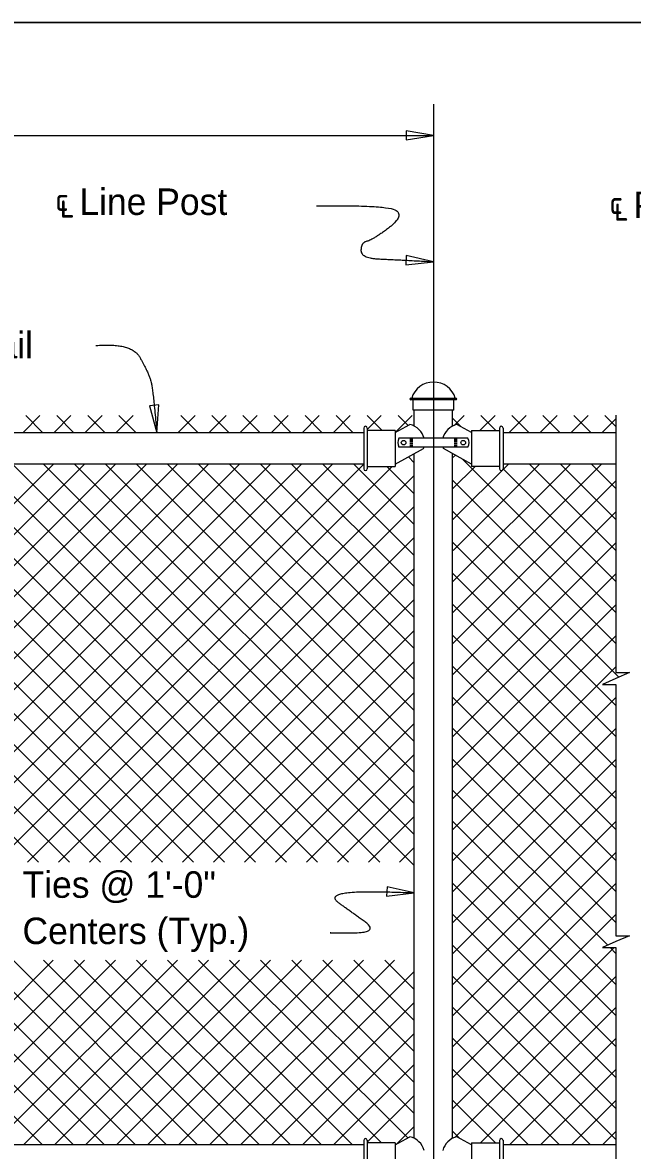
# Model space of a CAD drawing. Extents: x 0 to 41.1, y 0 to 25.9.
# Drawn here: x 18.95 to 23.59, y 17.37 to 25.95 of the extents above; entities that cross this region are included whole.
import ezdxf

# ---------------------------------------------------------------- set-up
doc = ezdxf.new("R2010")
doc.units = 0
for name, color, linetype in [('ActivePts-ConstElements', 7, 'Continuous'), ('CL_Major', 7, 'Continuous'), ('Dimension', 7, 'Continuous'), ('Miscellaneous', 7, 'Continuous'), ('Miscellaneous1', 7, 'Continuous'), ('SteelMisc', 7, 'Continuous'), ('TextStructures', 7, 'Continuous')]:
    doc.layers.add(name, color=color, linetype=linetype)

msp = doc.modelspace()

# ---------------------------------------------------------------- linework, layer by layer
at = {"layer": 'ActivePts-ConstElements'}
msp.add_lwpolyline([(0, 0), (41.0506, 0), (41.0506, 25.9461), (0, 25.9461)], close=True, dxfattribs=at)
at = {"layer": 'CL_Major'}
msp.add_line((22.075, 25.3255), (22.075, 16.5436), dxfattribs=at)
at = {"layer": 'Dimension'}
msp.add_line((2.075, 25.0883), (22.075, 25.0883), dxfattribs=at)
for points in [[(22.075, 25.0884), (21.8668, 25.1237), (21.8668, 25.0531)], [(22.075, 24.1273), (21.869, 24.1739), (21.8652, 24.1035)], [(19.9724, 22.8271), (19.9882, 23.0378), (19.9179, 23.0312)], [(21.9293, 19.3283), (21.7227, 19.3721), (21.7198, 19.3016)]]:
    msp.add_lwpolyline(points, close=True, dxfattribs=at)
for points in [[(23.462, 22.9593), (23.462, 21.0031), (23.5654, 21.0031), (23.462, 20.9581), (23.3587, 20.9131), (23.462, 20.9131), (23.462, 20.0194)], [(23.462, 20.0194), (23.462, 19.0017), (23.5654, 19.0017), (23.462, 18.9567), (23.3587, 18.9117), (23.462, 18.9117), (23.462, 16.9573)]]:
    msp.add_lwpolyline(points, dxfattribs=at)
for points in [[(21.1855, 24.5511), (21.7313, 24.5609), (21.8537, 24.472), (21.6095, 24.2907), (21.5247, 24.2723), (21.5247, 24.1544), (21.8027, 24.1422), (22.075, 24.1273)], [(19.5105, 23.4901), (19.7822, 23.5125), (19.9084, 23.2854), (19.9452, 23.1638), (19.9724, 22.827)], [(21.2967, 19.0236), (21.2533, 19.0236), (21.6734, 19.0236), (21.4231, 19.2007), (21.286, 19.3034), (21.4965, 19.3459), (21.9292, 19.3281)]]:
    msp.add_open_spline(points, degree=2, dxfattribs=at)
at = {"layer": 'Miscellaneous'}
for p, q in [((18.9555, 22.8271), (19.0857, 22.9573)), ((18.9782, 22.9573), (19.1084, 22.8271)), ((19.1912, 22.8271), (19.3214, 22.9573)), ((19.2139, 22.9573), (19.3441, 22.8271)), ((19.4269, 22.8271), (19.5571, 22.9573)), ((19.4496, 22.9573), (19.5798, 22.8271)), ((19.6626, 22.8271), (19.7928, 22.9573)), ((19.6853, 22.9573), (19.8155, 22.8271)), ((20.134, 22.8271), (20.2642, 22.9573)), ((20.1567, 22.9573), (20.2869, 22.8271)), ((20.3697, 22.8271), (20.4999, 22.9573)), ((20.3924, 22.9573), (20.5226, 22.8271)), ((20.6054, 22.8271), (20.7356, 22.9573)), ((20.6281, 22.9573), (20.7583, 22.8271)), ((20.8411, 22.8271), (20.9713, 22.9573)), ((20.8639, 22.9573), (20.994, 22.8271)), ((21.0768, 22.8271), (21.207, 22.9573)), ((21.0996, 22.9573), (21.2297, 22.8271)), ((21.3125, 22.8271), (21.4427, 22.9573)), ((21.3353, 22.9573), (21.4654, 22.8271)), ((21.571, 22.9573), (21.6857, 22.8425)), ((21.5725, 22.8513), (21.6784, 22.9573)), ((21.7855, 22.8286), (21.9141, 22.9573)), ((21.8067, 22.9573), (21.8824, 22.8815)), ((22.2209, 22.9364), (22.286, 22.8712)), ((22.2328, 22.8826), (22.3075, 22.9573)), ((22.4284, 22.8425), (22.5432, 22.9573)), ((22.4357, 22.9573), (22.5505, 22.8425)), ((22.6487, 22.8271), (22.7789, 22.9573)), ((22.6714, 22.9573), (22.8016, 22.8271)), ((22.8844, 22.8271), (23.0146, 22.9573)), ((22.9071, 22.9573), (23.0373, 22.8271)), ((23.1201, 22.8271), (23.2503, 22.9573)), ((23.1428, 22.9573), (23.273, 22.8271)), ((23.3558, 22.8271), (23.462, 22.9332)), ((23.3785, 22.9573), (23.462, 22.8738)), ((22.2209, 22.635), (22.2422, 22.6562)), ((15.1887, 17.4104), (20.3658, 22.5875)), ((15.4244, 17.4104), (20.6015, 22.5875)), ((15.6601, 17.4104), (20.8372, 22.5875)), ((15.8958, 17.4104), (21.073, 22.5875)), ((16.1315, 17.4104), (21.3087, 22.5875)), ((16.3672, 17.4104), (21.5457, 22.5888)), ((16.6029, 17.4104), (21.7628, 22.5703)), ((16.7553, 22.5875), (19.7812, 19.5616)), ((16.991, 22.5875), (20.0169, 19.5616)), ((17.2267, 22.5875), (20.2526, 19.5616)), ((17.4624, 22.5875), (20.4883, 19.5616)), ((17.6981, 22.5875), (20.724, 19.5616)), ((17.8268, 21.227), (19.1873, 22.5875)), ((17.9338, 22.5875), (20.9597, 19.5616)), ((18.0625, 21.227), (19.423, 22.5875)), ((18.1657, 21.0945), (19.6587, 22.5875)), ((18.1657, 20.6231), (20.1301, 22.5875)), ((18.1657, 20.8588), (19.8944, 22.5875)), ((18.1695, 22.5875), (21.1954, 19.5616)), ((18.4052, 22.5875), (21.4311, 19.5616)), ((18.6409, 22.5875), (21.6668, 19.5616)), ((18.8766, 22.5875), (21.9292, 19.5349)), ((19.1123, 22.5875), (21.9292, 19.7706)), ((19.348, 22.5875), (21.9292, 20.0063)), ((19.5837, 22.5875), (21.9292, 20.242)), ((19.8194, 22.5875), (21.9292, 20.4777)), ((20.0551, 22.5875), (21.9292, 20.7134)), ((20.2908, 22.5875), (21.9292, 20.9491)), ((20.5265, 22.5875), (21.9292, 21.1848)), ((20.7622, 22.5875), (21.9292, 21.4205)), ((20.9979, 22.5875), (21.9292, 21.6562)), ((21.2336, 22.5875), (21.9292, 21.8919)), ((21.4693, 22.5875), (21.9292, 22.1276)), ((21.7222, 22.5703), (21.9292, 22.3633)), ((21.8848, 22.6434), (21.9292, 22.599)), ((22.2209, 21.4565), (23.3519, 22.5875)), ((22.2209, 21.6922), (23.1162, 22.5875)), ((22.2209, 22.1636), (22.6448, 22.5875)), ((22.2209, 22.3993), (22.3919, 22.5703)), ((22.2253, 21.9323), (22.8805, 22.5875)), ((22.2942, 22.6274), (23.462, 21.4596)), ((22.8055, 22.5875), (23.462, 21.931)), ((23.0412, 22.5875), (23.462, 22.1667)), ((23.2769, 22.5875), (23.462, 22.4024)), ((18.9899, 19.5616), (21.9292, 22.501)), ((22.6044, 22.5529), (23.462, 21.6953)), ((22.2209, 22.465), (23.462, 21.2239)), ((22.2209, 21.2208), (23.462, 22.4618)), ((19.2256, 19.5616), (21.9292, 22.2653)), ((22.2209, 22.2293), (23.483, 20.9671)), ((22.2209, 20.985), (23.462, 22.2261)), ((19.4613, 19.5616), (21.9292, 22.0296)), ((22.2209, 21.9936), (23.462, 20.7525)), ((22.2209, 20.7493), (23.462, 21.9904)), ((19.697, 19.5616), (21.9292, 21.7939)), ((22.2209, 21.7579), (23.462, 20.5168)), ((22.2209, 20.5136), (23.462, 21.7547)), ((19.9327, 19.5616), (21.9292, 21.5582)), ((22.2209, 21.5222), (23.462, 20.2811)), ((22.2209, 20.2779), (23.462, 21.519)), ((20.1684, 19.5616), (21.9292, 21.3225)), ((22.2209, 21.2865), (23.462, 20.0454)), ((22.2209, 20.0422), (23.462, 21.2833)), ((20.4041, 19.5616), (21.9292, 21.0868)), ((22.2209, 21.0508), (23.462, 19.8097)), ((22.2209, 19.8065), (23.462, 21.0476)), ((18.1657, 20.9414), (19.5454, 19.5616)), ((20.6398, 19.5616), (21.9292, 20.8511)), ((22.2209, 20.8151), (23.462, 19.574)), ((22.2209, 19.5708), (23.462, 20.8119)), ((18.1657, 20.7057), (19.3097, 19.5616)), ((20.8755, 19.5616), (21.9292, 20.6154)), ((16.0047, 20.5096), (19.104, 17.4104)), ((16.2404, 20.5096), (19.3397, 17.4104)), ((16.4761, 20.5096), (19.5754, 17.4104)), ((16.7118, 20.5096), (19.8111, 17.4104)), ((16.9475, 20.5096), (20.0468, 17.4104)), ((17.1832, 20.5096), (20.2825, 17.4104)), ((18.126, 20.5096), (19.074, 19.5616)), ((22.2209, 20.5794), (23.462, 19.3383)), ((22.2209, 19.3351), (23.462, 20.5762)), ((21.1112, 19.5616), (21.9292, 20.3797)), ((22.2209, 20.3437), (23.462, 19.1026)), ((22.2209, 19.0994), (23.462, 20.3405)), ((21.3469, 19.5616), (21.9292, 20.1439)), ((22.2209, 20.108), (23.3995, 18.9294)), ((22.2209, 18.8637), (23.462, 20.1048)), ((21.5826, 19.5616), (21.9292, 19.9082)), ((22.2209, 19.8723), (23.462, 18.6312)), ((22.2209, 18.628), (23.462, 19.8691)), ((21.8183, 19.5616), (21.9292, 19.6725)), ((22.2209, 19.6366), (23.462, 18.3955)), ((22.2209, 18.3923), (23.462, 19.6334)), ((22.2209, 19.4009), (23.462, 18.1598)), ((22.2209, 18.1566), (23.462, 19.3977)), ((22.2209, 19.1652), (23.462, 17.9241)), ((22.2209, 17.9209), (23.462, 19.162)), ((22.2209, 18.9295), (23.462, 17.6884)), ((22.2209, 17.6852), (23.4473, 18.9116)), ((23.4172, 18.9116), (23.462, 18.8669)), ((17.7814, 17.4104), (19.1871, 18.8161)), ((18.0171, 17.4104), (19.4228, 18.8161)), ((18.2528, 17.4104), (19.6585, 18.8161)), ((18.4885, 17.4104), (19.8942, 18.8161)), ((18.7242, 17.4104), (20.1299, 18.8161)), ((18.9599, 17.4104), (20.3656, 18.8161)), ((19.1125, 18.8161), (20.5182, 17.4104)), ((19.1956, 17.4104), (20.6013, 18.8161)), ((19.3482, 18.8161), (20.7539, 17.4104)), ((19.4313, 17.4104), (20.837, 18.8161)), ((19.5839, 18.8161), (20.9896, 17.4104)), ((19.6671, 17.4104), (21.0727, 18.8161)), ((19.8196, 18.8161), (21.2253, 17.4104)), ((19.9028, 17.4104), (21.3084, 18.8161)), ((20.0553, 18.8161), (21.461, 17.4104)), ((20.1385, 17.4104), (21.5441, 18.8161)), ((20.291, 18.8161), (21.6813, 17.4258)), ((20.3742, 17.4104), (21.7798, 18.8161)), ((20.5267, 18.8161), (21.8796, 17.4632)), ((20.7624, 18.8161), (21.9292, 17.6492)), ((20.9981, 18.8161), (21.9292, 17.8849)), ((21.2338, 18.8161), (21.9292, 18.1206)), ((21.4695, 18.8161), (21.9292, 18.3563)), ((21.7052, 18.8161), (21.9292, 18.592)), ((20.6099, 17.4104), (21.9292, 18.7297)), ((22.2209, 18.6938), (23.462, 17.4527)), ((22.2398, 17.4684), (23.462, 18.6906)), ((20.8456, 17.4104), (21.9292, 18.494)), ((22.2209, 18.4581), (23.2686, 17.4104)), ((22.4329, 17.4258), (23.462, 18.4549)), ((21.0813, 17.4104), (21.9292, 18.2583)), ((22.2209, 18.2224), (23.0329, 17.4104)), ((22.6532, 17.4104), (23.462, 18.2192)), ((21.317, 17.4104), (21.9292, 18.0226)), ((22.2209, 17.9866), (22.7972, 17.4104)), ((22.8889, 17.4104), (23.462, 17.9835)), ((21.5725, 17.4302), (21.9292, 17.7869)), ((22.2209, 17.7509), (22.546, 17.4258)), ((23.1246, 17.4104), (23.462, 17.7478)), ((21.7935, 17.4155), (21.9292, 17.5512)), ((22.2209, 17.5152), (22.2761, 17.46)), ((23.3603, 17.4104), (23.462, 17.5121))]:
    msp.add_line(p, q, dxfattribs=at)
at = {"layer": 'Miscellaneous1'}
msp.add_lwpolyline([(0, 25.9461), (41.0506, 25.9461), (41.0506, 0), (0, 0)], close=True, dxfattribs=at)
at = {"layer": 'SteelMisc'}
for p, q in [((21.9028, 23.0892), (22.2473, 23.0892)), ((22.2473, 23.077), (21.9028, 23.077)), ((21.921, 22.9972), (21.921, 23.077)), ((22.2291, 22.9972), (22.2291, 23.077)), ((22.2291, 22.9972), (21.921, 22.9972)), ((21.9292, 22.8773), (21.9292, 22.9972)), ((22.2209, 22.8773), (22.2209, 22.9972)), ((21.5457, 22.8271), (12.6044, 22.8271)), ((21.5457, 22.8621), (21.5457, 22.5524)), ((21.5725, 22.8621), (21.5725, 22.5524)), ((21.7855, 22.8425), (21.5725, 22.8425)), ((21.7855, 22.8278), (21.8963, 22.8892)), ((21.7855, 22.8425), (21.7855, 22.5703)), ((22.3646, 22.8278), (22.2537, 22.8892)), ((22.3646, 22.8425), (22.3646, 22.5703)), ((22.3646, 22.8425), (22.5775, 22.8425)), ((22.5775, 22.8621), (22.5775, 22.5524)), ((22.6044, 22.8621), (22.6044, 22.5524)), ((23.462, 22.8271), (22.6044, 22.8271)), ((22.3374, 22.7852), (21.8126, 22.7852)), ((21.895, 22.7774), (21.9185, 22.7774)), ((21.895, 22.7678), (21.9185, 22.7678)), ((21.895, 22.757), (21.9185, 22.757)), ((21.895, 22.7452), (21.9185, 22.7452)), ((21.895, 22.7334), (21.9185, 22.7334)), ((22.255, 22.7774), (22.2316, 22.7774)), ((22.255, 22.7678), (22.2316, 22.7678)), ((22.255, 22.757), (22.2316, 22.757)), ((22.255, 22.7452), (22.2316, 22.7452)), ((22.255, 22.7334), (22.2316, 22.7334)), ((21.7855, 22.5884), (21.9994, 22.707)), ((22.3374, 22.7174), (21.8126, 22.7174)), ((21.895, 22.7236), (21.9185, 22.7236)), ((21.9292, 17.4606), (21.9292, 22.6681)), ((22.3646, 22.5884), (22.1506, 22.707)), ((22.2209, 17.4606), (22.2209, 22.668)), ((22.255, 22.7236), (22.2316, 22.7236)), ((21.5457, 22.5875), (12.6044, 22.5875)), ((21.5725, 22.5703), (21.7855, 22.5703)), ((22.5775, 22.5703), (22.3646, 22.5703)), ((23.462, 22.5875), (22.6044, 22.5875)), ((21.5457, 17.4454), (21.5457, 17.1357)), ((21.5725, 17.4454), (21.5725, 17.1357)), ((21.7855, 17.4258), (21.5725, 17.4258)), ((21.7855, 17.4111), (21.8963, 17.4724)), ((21.7855, 17.4258), (21.7855, 17.1536)), ((22.3646, 17.4111), (22.2537, 17.4724)), ((22.3646, 17.4258), (22.3646, 17.1536)), ((22.3646, 17.4258), (22.5775, 17.4258)), ((22.5775, 17.4454), (22.5775, 17.1357)), ((22.6044, 17.4454), (22.6044, 17.1357)), ((21.5457, 17.4104), (12.6044, 17.4104)), ((23.462, 17.4104), (22.6044, 17.4104))]:
    msp.add_line(p, q, dxfattribs=at)
for centre, radius, start, end in [((21.9029, 23.0829), 0.00613, 91.1647, 268.8353), ((22.2472, 23.0829), 0.00613, 271.1647, 88.8353), ((21.5592, 22.862), 0.0134, 0, 180), ((22.5909, 22.862), 0.0134, 0, 180), ((21.5592, 22.5522), 0.0134, 180, 0), ((22.5909, 22.5522), 0.0134, 180, 0), ((21.5592, 17.4453), 0.0134, 0, 180), ((22.5909, 17.4453), 0.0134, 0, 180)]:
    msp.add_arc(centre, radius, start, end, dxfattribs=at)
for centre, major_axis, start_param, end_param in [((22.0757, 23.0482), (0.1711, 0), 0.252602, 2.888574), ((21.8618, 22.7532), (0.146, 0), 0.231126, 1.331255), ((22.2882, 22.7532), (-0.146, 0), 4.95193, 6.05206), ((21.8818, 22.7512), (-0.0776, 0), 5.810211, 6.75616), ((22.2683, 22.7512), (0.0776, 0), 5.810211, 6.75616), ((21.8618, 22.7532), (0.146, 0), 5.947976, 6.024627), ((22.2882, 22.7532), (-0.146, 0), 0.258558, 0.335209), ((21.8618, 17.3365), (0.146, 0), 0.231126, 1.331255), ((22.2882, 17.3365), (-0.146, 0), 4.95193, 6.05206)]:
    msp.add_ellipse(centre, major_axis=major_axis, ratio=0.957868, start_param=start_param, end_param=end_param, dxfattribs=at)
for centre, major_axis in [((21.8485, 22.7508), (0.0178, 0)), ((22.3016, 22.7508), (-0.0178, 0))]:
    msp.add_ellipse(centre, major_axis=major_axis, ratio=0.957868, dxfattribs=at)

# ---------------------------------------------------------------- texts
at = {"layer": 'Dimension'}
for s, p in [('Ties @ 1\'-0" ', (18.9528, 19.2898)), ('Centers (Typ.)', (18.9528, 18.9378))]:
    msp.add_text(s, height=0.2016, dxfattribs=at).set_placement(p)
at = {"layer": 'TextStructures'}
for s, p in [('℄ Line Post', (19.2003, 24.4829)), ('℄ Pull Post', (23.4113, 24.4589)), ('Horizontal Rail', (17.2797, 23.3931))]:
    msp.add_text(s, height=0.2016, dxfattribs=at).set_placement(p)

doc.saveas('drawing.dxf')
